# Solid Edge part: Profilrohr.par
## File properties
Username: ahadarics
Dokumentum tartalom típus: 0
Author: ahadarics
Last saved by: ahadarics
Revision: 79
Sűrűség: 0,000 kg/m^3
Pontosság: 0,990
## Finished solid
Body 1: solid body, 115 faces, 338 edges, 224 vertices.
  Faces by surface: cylinder 59, plane 56
  Edges by curve: line 220, circle 118
Bounding box of the edges (mm): 95.500 x 95.500 x 44.000, from (-47.75, -47.75, -15) to (47.75, 47.75, 29).
Cylindrical faces by radius (mm): R0.2 x24, R0.5 x24, R1 x4, R10 x4, R13.5 x2, R40 x1
Planar faces by outward normal: +x 13, +y 14, +z 1, -x 13, -y 14, -z 1
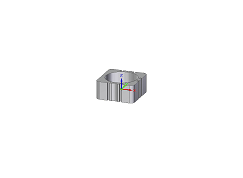
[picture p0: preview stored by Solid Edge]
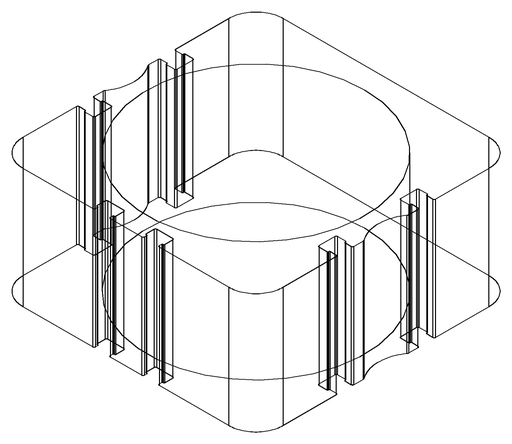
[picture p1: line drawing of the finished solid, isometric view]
